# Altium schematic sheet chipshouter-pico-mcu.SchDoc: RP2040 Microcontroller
size Letter; Organization: NewAE Technology Inc.; Address1: 1083 Queen St., Suite 196; Address2: Halifax; Address3: NS; Address4: Canada B3H 0B2; DocumentNumber: .; Revision: .; SheetNumber: 2; SheetTotal: 2; SheetApproved: YES
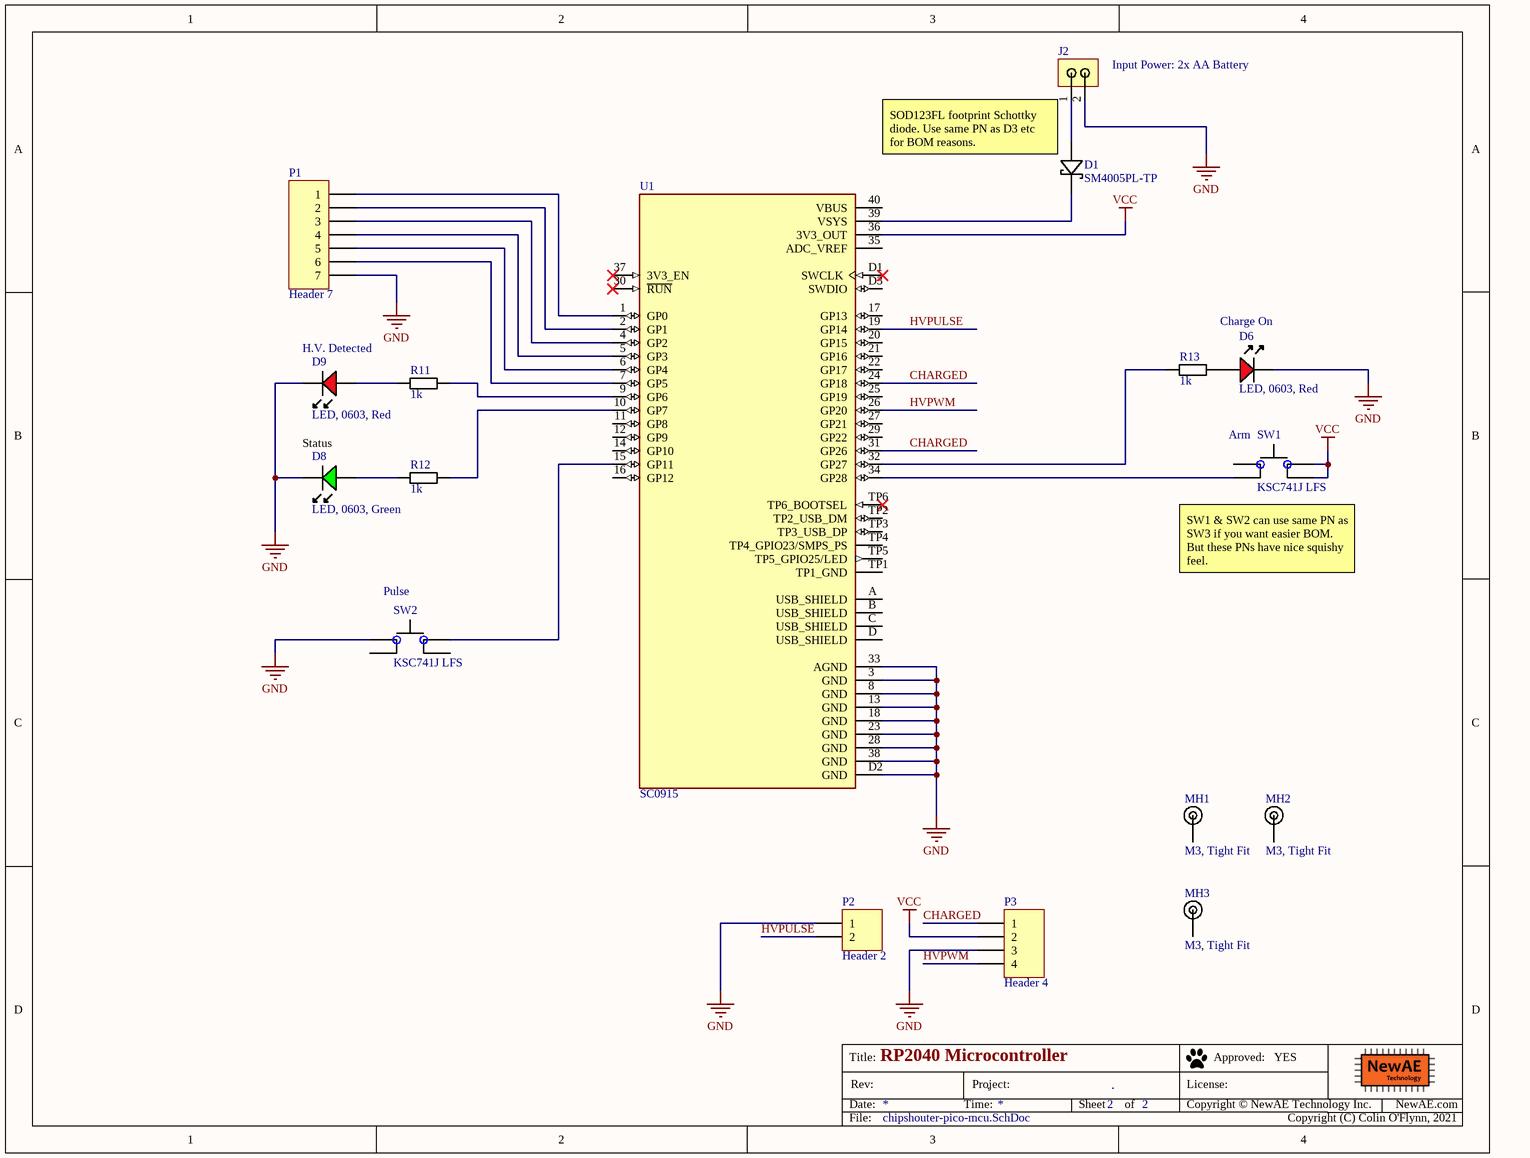
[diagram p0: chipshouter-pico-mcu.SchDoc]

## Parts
D1  SM4005PL-TP  [DSS13UTR]
D6  LED, 0603, Red  [LED-0603-RED]
D8  LED, 0603, Green  [LED-0603-GREEN]
D9  LED, 0603, Red  [LED-0603-RED]
J2  1x2_Pin_Header  [22-23-2021]  (value not drawn)
MH1  M3, Tight Fit  [MOUNT_M3_TIGHT]
MH2  M3, Tight Fit  [MOUNT_M3_TIGHT]
MH3  M3, Tight Fit  [MOUNT_M3_TIGHT]
P1  Header 7  [HDR1X7]
P2  Header 2  [HDR1X2]
P3  Header 4  [HDR1X4]
R11  1k  [RESC1608X55N]
R12  1k  [RESC1608X55N]
R13  1k  [RESC1608X55N]
SW1  KSC741J LFS  [CK_KSC7J]
SW2  KSC741J LFS  [CK_KSC7J]
U1  SC0915  [MODULE_SC0915_TH]

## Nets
GND: D6.K D8.K D9.K J2.2 P1.7 P2.1 P3.3 SW2.1(IN) U1.3(GND) U1.8(GND) U1.13(GND) U1.18(GND) U1.23(GND) U1.28(GND) U1.33(AGND) U1.38(GND) U1.D2(GND)
VCC: P3.2 SW1.2(IN) SW1.3(IN) U1.36(3V3_OUT)
CHARGED: P3.1 U1.24(GP18) U1.31(GP26)
HVPULSE: P2.2 U1.19(GP14)
HVPWM: P3.4 U1.26(GP20)
NetD1_A: D1.A J2.1
NetD1_K: D1.K U1.39(VSYS)
NetD6_A: D6.A R13.1
NetD8_A: D8.A R12.1
NetD9_A: D9.A R11.1
NetP1_1: P1.1 U1.1(GP0)
NetP1_2: P1.2 U1.2(GP1)
NetP1_3: P1.3 U1.4(GP2)
NetP1_4: P1.4 U1.5(GP3)
NetP1_5: P1.5 U1.6(GP4)
NetP1_6: P1.6 U1.7(GP5)
NetR11_2: R11.2 U1.9(GP6)
NetR12_2: R12.2 U1.10(GP7)
NetR13_2: R13.2 U1.32(GP27)
NetSW1_4: SW1.4(IN) U1.34(GP28)
NetSW2_2: SW2.2(IN) U1.15(GP11)

Not connected (* = marked no-connect by the designer): MH1 1; MH2 1; MH3 1; SW1 1(IN); SW2 3(IN) 4(IN); U1 11(GP8) 12(GP9) 14(GP10) 16(GP12) 17(GP13) 20(GP15) 21(GP16) 22(GP17) 25(GP19) 27(GP21) 29(GP22) 30(~{RUN})* 35(ADC_VREF) 37(3V3_EN)* 40(VBUS) A(USB_SHIELD) B(USB_SHIELD) C(USB_SHIELD) D(USB_SHIELD) D1(SWCLK)* D3(SWDIO) TP1(TP1_GND) TP2(TP2_USB_DM) TP3(TP3_USB_DP) TP4(TP4_GPIO23/SMPS_PS) TP5(TP5_GPIO25/LED) TP6(TP6_BOOTSEL)*

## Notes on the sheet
- (near J2) Input Power: 2x AA Battery
- (near D1) SOD123FL footprint Schottky diode. Use same PN as D3 etc for BOM reasons.
- H.V. Detected
- Charge On
- (near SW1) Arm
- Status
- (near SW1) SW1 & SW2 can use same PN as SW3 if you want easier BOM. But these PNs have nice squishy feel.
- (near SW2) Pulse
- Copyright (C) Colin O'Flynn, 2021

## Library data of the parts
D1 = DSS13UTR: SCHOTTKY 30V SOD-123FL; Manufacture 1: MCC; Component Group: Diode; PP Material Stack: 0
D6 D9 = LEDCHIP_0603_RED: Chip LED, Red; Manufacture 1: Kingbright; Manufacture Part Number 1: APT1608SRCPRV; Component Group: Optical; PP Material Stack: 15; PP Rotation: -90
D8 = LEDCHIP_0603_GREEN: Chip LED, Green; Manufacture 1: Kingbright; Manufacture Part Number 1: APT1608CGCK; Component Group: Optical; PP Material Stack: 16; PP Rotation: -90
J2 = Molex_2_Pin: CONN HEADER 2POS .100 VERT TIN; Manufacture 1: Molex; Manufacture Part Number 1: 22-23-2021 / 22-23-2021; Component Group: Connector; PP Material Stack: 0
MH1-MH3 = MOUNT_M3_TIGHT: Machine screw M3 Mounting Hole; Component Group: Mechanical; PP Material Stack: 0
P1 = Header 7: Header, 7-Pin
P2 = Header 2: Header, 2-Pin
P3 = Header 4: Header, 4-Pin
R11-R13 = RCHIP-1K-0603: 1k res, 0603, 1%, 1/10W; Manufacture 1: Yageo; Manufacture Part Number 1: RC0603FR-071KL; Component Group: Resistor; Case-EIA: 0603; Case-Metric: 1608; Rated Power: 0.1W; Rated Voltage: 75VDC
SW1 SW2 = TACTSW-KSC741J: SWITCH TACTILE SPST-NO 0.01A 32V; Manufacture 1: C&K; PP Material Stack: 0
U1 = SC0915: Raspberry Pi Pico; Component Group: PCB Feature; PP Material Stack: 0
